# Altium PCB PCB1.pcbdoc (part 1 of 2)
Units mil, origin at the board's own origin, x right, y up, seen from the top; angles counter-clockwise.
Board outline 5175 x 2060 mil, 4 copper layers (Top Layer, Inner1, Inner2, Bottom Layer), stack 62.447 mil thick; 105 components, 59 nets, 317 pads, 174 vias.
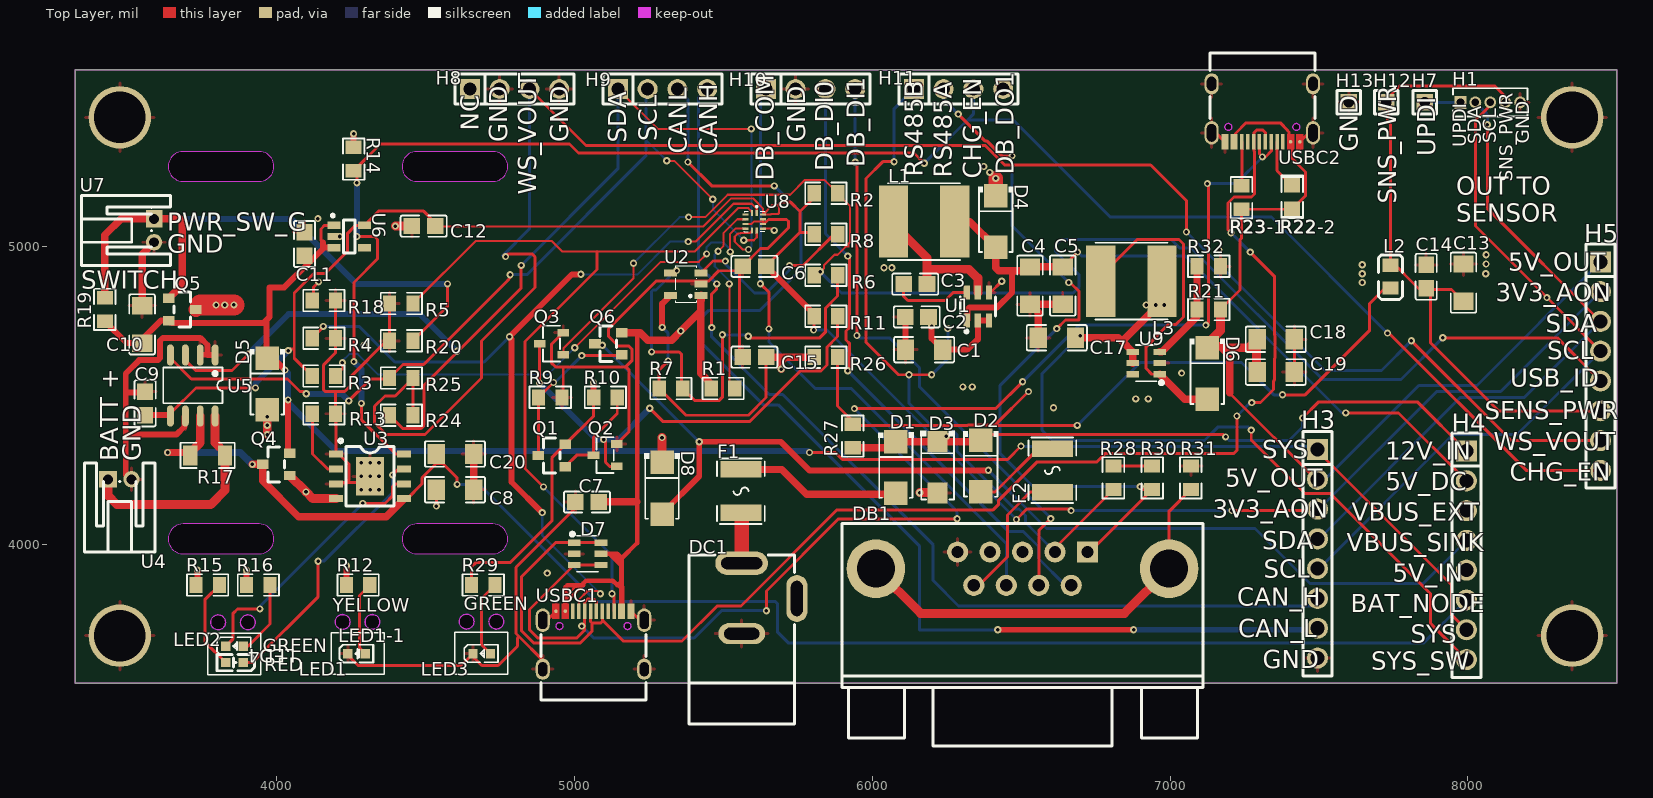
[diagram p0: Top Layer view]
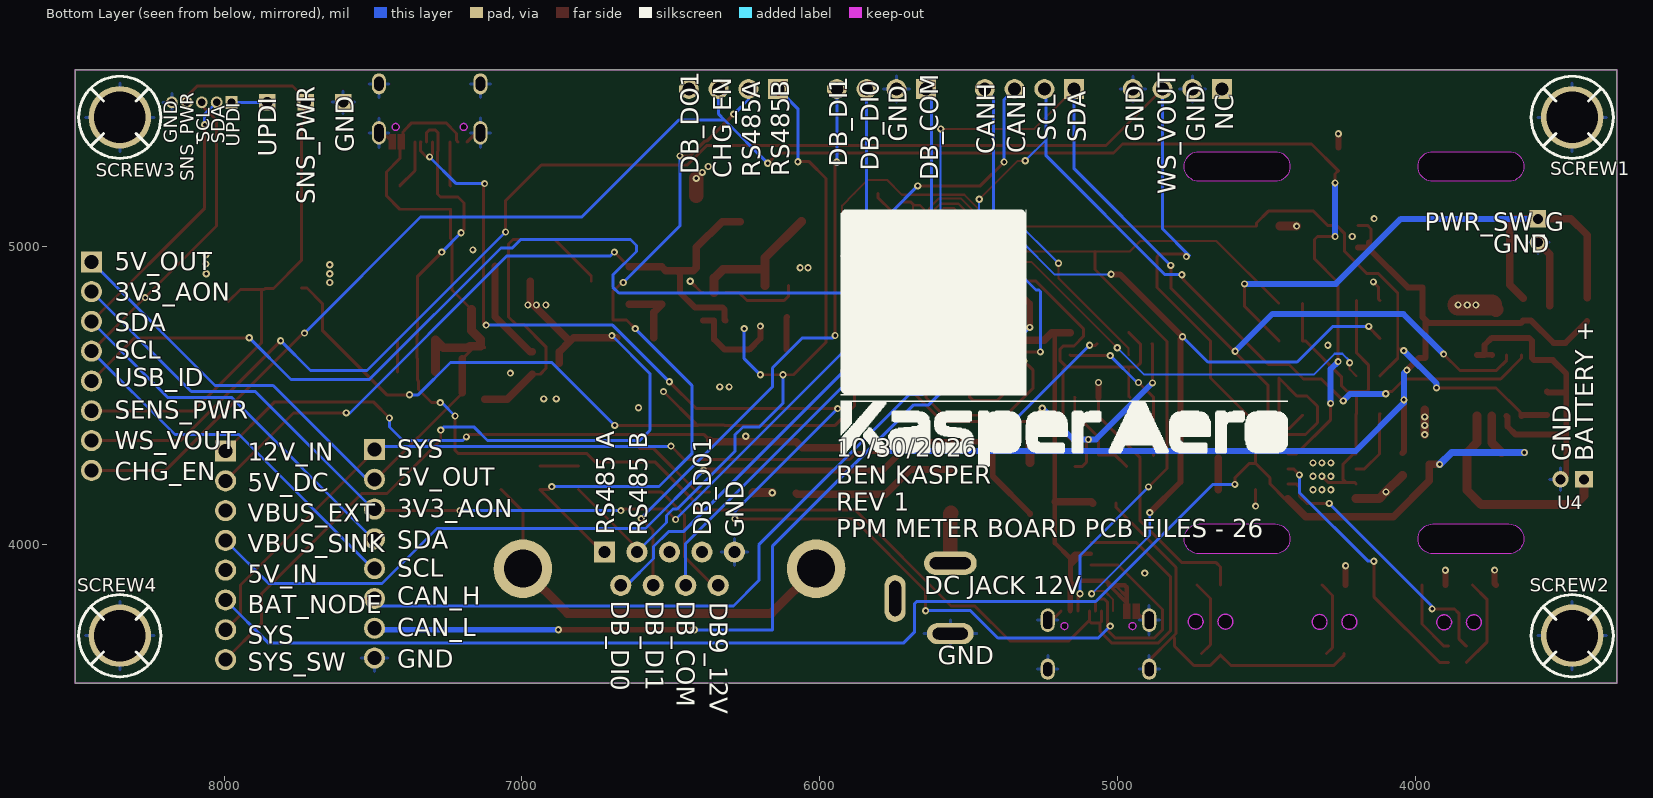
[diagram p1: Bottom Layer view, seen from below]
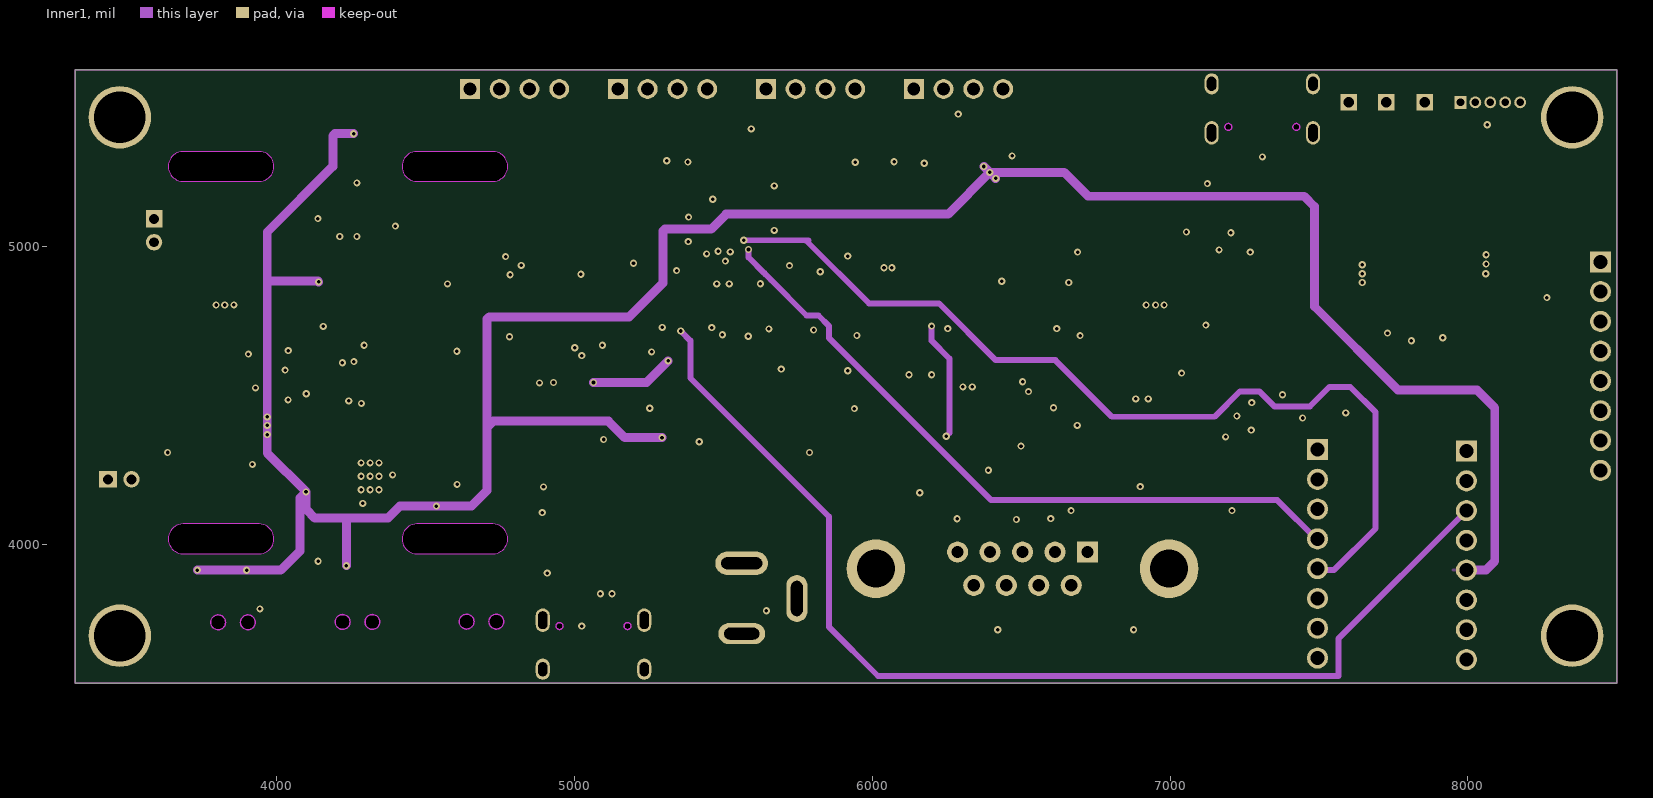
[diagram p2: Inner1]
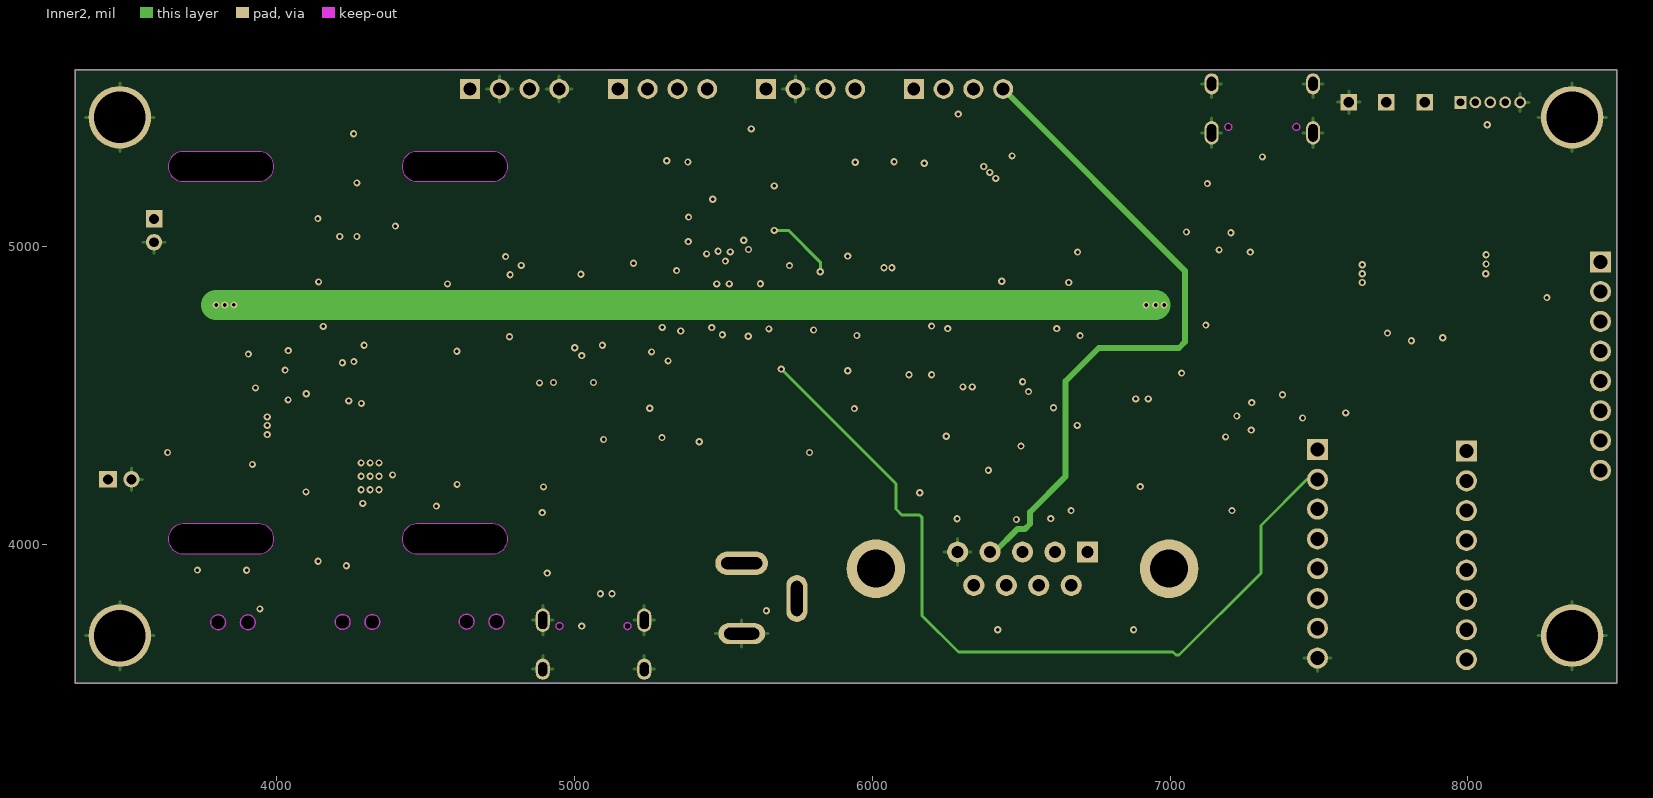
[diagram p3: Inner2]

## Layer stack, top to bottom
Top Layer: signal copper 1.378
Dielectric1: surface 8.283, 7628 RC49% 8.6mil, Dk 0
Inner1: signal copper 0.598
Dielectric2: surface 41.929, 1.1mm H/HOZ Copper, Dk 0
Inner2: signal copper 0.598
Dielectric3: surface 8.283, 7628 RC49% 8.6mil, Dk 0
Bottom Layer: signal copper 1.378

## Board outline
3325,5595 3325,3535 8500,3535 8500,5595
cut-out: 3687.5,5320 ccw(c3687.5,5270) 3637.5,5270 ccw(c3687.5,5270) 3687.5,5220 3942.5,5220 ccw(c3942.5,5270) 3992.5,5270 ccw(c3942.5,5270) 3942.5,5320
cut-out: 4472.5,5320 ccw(c4472.5,5270) 4422.5,5270 ccw(c4472.5,5270) 4472.5,5220 4727.5,5220 ccw(c4727.5,5270) 4777.5,5270 ccw(c4727.5,5270) 4727.5,5320
cut-out: 3687.5,4070 ccw(c3687.5,4020) 3637.5,4020 ccw(c3687.5,4020) 3687.5,3970 3942.5,3970 ccw(c3942.5,4020) 3992.5,4020 ccw(c3942.5,4020) 3942.5,4070
cut-out: 4472.5,4070 ccw(c4472.5,4020) 4422.5,4020 ccw(c4472.5,4020) 4472.5,3970 4727.5,3970 ccw(c4727.5,4020) 4777.5,4020 ccw(c4727.5,4020) 4727.5,4070
cut-out: 3830,3740 cw(c3805,3740) 3780,3740 cw(c3805,3740)
cut-out: 3930,3740 cw(c3905,3740) 3880,3740 cw(c3905,3740)
cut-out: 4248,3741.25 cw(c4223,3741.25) 4198,3741.25 cw(c4223,3741.25)
cut-out: 4348,3741.25 cw(c4323,3741.25) 4298,3741.25 cw(c4323,3741.25)
cut-out: 4664,3742.25 cw(c4639,3742.25) 4614,3742.25 cw(c4639,3742.25)
cut-out: 4764,3742.3 cw(c4739,3742.3) 4714,3742.3 cw(c4739,3742.3)

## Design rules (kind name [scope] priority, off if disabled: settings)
BoardOutlineClearance copperThickness1oz [All] p0: genericclearance=10 ignorepadtopadclearanceinfootprint=FALSE except(0: Arc-SplitContinuation Track-SplitContinuation SMDPad-SplitContinuation THPad-SplitContinuation Via-SplitContinuation Fill-SplitContinuation Poly-SplitContinuation Region-SplitContinuation Text-SplitContinuation)
BoardOutlineClearance copperThickness2oz [All] p0: genericclearance=10 ignorepadtopadclearanceinfootprint=FALSE except(0: Arc-SplitContinuation Track-SplitContinuation SMDPad-SplitContinuation THPad-SplitContinuation Via-SplitContinuation Fill-SplitContinuation Poly-SplitContinuation Region-SplitContinuation Text-SplitContinuation)
BoardOutlineClearance safeClearance1 [All] p0: genericclearance=10 ignorepadtopadclearanceinfootprint=FALSE except(0: Arc-SplitContinuation Track-SplitContinuation SMDPad-SplitContinuation THPad-SplitContinuation Via-SplitContinuation Fill-SplitContinuation Poly-SplitContinuation Region-SplitContinuation Text-SplitContinuation)
BoardOutlineClearance otherClearance [All] p0: genericclearance=10 ignorepadtopadclearanceinfootprint=FALSE except(0: Arc-SplitContinuation Track-SplitContinuation SMDPad-SplitContinuation THPad-SplitContinuation Via-SplitContinuation Fill-SplitContinuation Poly-SplitContinuation Region-SplitContinuation Text-SplitContinuation)
Clearance copperThickness1oz [All] p1: gap=7 ignorepadtopadclearanceinfootprint=FALSE
Clearance copperThickness2oz [All] p1: gap=7 ignorepadtopadclearanceinfootprint=FALSE
Clearance safeClearance1 [All] p1: gap=7 ignorepadtopadclearanceinfootprint=FALSE
Clearance otherClearance [All] p1: gap=7 ignorepadtopadclearanceinfootprint=FALSE
DiffPairsRouting differentialPair [All] p1: maxuncoupledlength=10 minlimit=6 maxlimit=Infinity mostfreqgap=6 toplayer_minwidth=5 toplayer_prefwidth=10 toplayer_maxwidth=100 bottomlayer_minwidth=5 bottomlayer_prefwidth=10 bottomlayer_maxwidth=100 midlayer1_minwidth=5 midlayer1_prefwidth=10 midlayer1_maxwidth=100 midlayer2_minwidth=5 midlayer2_prefwidth=10 midlayer2_maxwidth=100
PasteMaskExpansion pasteMaskExpansion [All] p1: expansion=0
PlaneConnect innerPlane [All] p1: planeconnectstyle=Relief reliefexpansion=20 reliefentries=4 reliefconductorwidth=10 reliefairgap=10
PolygonConnect copperRegion [All] p1: connectstyle=Relief reliefentries=4 reliefconductorwidth=10 polygonreliefangle="90 Angle" airgapwidth=10
RoutingVias viaSize [All] p1: viastyle="Through Hole" holewidth=12.0078 minholewidth=11.811 maxholewidth=248.0314 width=12.0078 minwidth=11.811 maxwidth=248.0314
SolderMaskExpansion solderMaskExpansion [IsVia] p1: useseparateexpansions=TRUE expansion=-1000 expansionbottom=-1000
SolderMaskExpansion solderMaskExpansion [All] p2: useseparateexpansions=TRUE expansion=2 expansionbottom=2
Width copperThickness1oz [All] p1: maxlimit=100 minlimit=5 preferedwidth=10
Width copperThickness2oz [All] p1: maxlimit=100 minlimit=8 preferedwidth=10

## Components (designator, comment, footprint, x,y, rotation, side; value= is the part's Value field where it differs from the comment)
C1 "22uF" C1206 6175,4655 r0 top
C2 "100nF" C0805 6150,4765 r0 top
C3 "100nF" C0805 6145,4875 r180 top
C4 "22uF" C1206 6530,4870 r90 top
C5 "22uF" C1206 6640,4870 r90 top
C6 "100nF" C0805 5605,4935 r0 top
C7 "1uF" C0805 5043.2,4143.7 r180 top
C8 "22uF" C1206 4600,4185 r180 top
C9 "100nF" C0805 3560,4475 r270 top
C10 "22uF" C1206 3550,4740 r270 top
C11 "1uF" C0805 4095,5010 r270 top
C12 "1uF" C0805 4495,5070 r0 top
C13 "22uF" C1206 7985,4880 r90 top
C14 "100nF" C0805 7860,4900 r270 top
C15 "100nF" C0805 5605,4630 r0 top
C17 "22uF" C1206 6620,4695 r180 top
C18 "22uF" C1206 7355,4690 r0 top
C19 "22uF" C1206 7355,4580 r0 top
C20 "22uF" C1206 4600,4305 r180 top
D1 "SS34" SMA_L4.3-W2.6-LS5.2-RD 6080,4260 r270 top
D2 "SS34" SMA_L4.3-W2.6-LS5.2-RD 6365,4264.23 r270 top
D3 "SMAJ18A" SMA_L4.4-W2.6-LS5.0-RD 6220,4260 r270 top
D4 "SS34" SMA_L4.3-W2.6-LS5.2-RD 6415,5085 r270 top
D5 "SS34" SMA_L4.3-W2.6-LS5.2-RD 3970,4540 r270 top
D6 "SS34" SMA_L4.3-W2.6-LS5.2-RD 7125,4575 r270 top
D7 "USBLC6-2SC6" SOT-23-6_L2.9-W1.6-P0.95-LS2.8-BL 5045,3970 r270 top
D8 "SS34" SMA_L4.3-W2.6-LS5.2-RD 5295,4190 r270 top
DB1 "A-DF 09 A/KG-T2S" DB9-TH_DB9F_C9900018961 6505,3920 r0 top
DC1 "PJ-002AH" DC-IN-TH_PJ-002AH 5655,3820 r270 top
F1 "BSMD1812-150-33V" F1812 5560,4180 r90 top
F2 "BSMD1812-150-33V" F1812 6605,4250 r90 top
H1 "GRPB051VWVN-RC" HDR-TH_5P-P1.27-V-M-1 8075,5485 r0 top
H3 "" HDR-TH_8P-P2.54-V-F-1 7495,3970 r270 top
H4 "" HDR-TH_8P-P2.54-V-F-1 7995,3965 r270 top
H5 "" HDR-TH_8P-P2.54-V-F-1 8445,4600 r270 top
H7 "" HDR-TH_1P-V-M_XKB_X4611WV-01I-C28D40 7855,5485.98 r0 top
H8 "" HDR-TH_4P-P2.54-V-M 4800,5530 r0 top
H9 "" HDR-TH_4P-P2.54-V-M 5296.67,5530 r0 top
H10 "" HDR-TH_4P-P2.54-V-M 5793.33,5530 r0 top
H11 "" HDR-TH_4P-P2.54-V-M 6290,5530 r0 top
H12 "" HDR-TH_1P-V-M_XKB_X4611WV-01I-C28D40 7726.37,5485.98 r0 top
H13 "" HDR-TH_1P-V-M_XKB_X4611WV-01I-C28D40 7600,5485.98 r0 top
L1 "6.8uH" IND-SMD_L6.0-W6.0_SMNR6045 6175,5085 r180 top
L2 "BLM21PG221SN1D" L0805 7740,4900 r90 top
L3 "6.8uH" IND-SMD_L6.0-W6.0_SMNR6045 6870,4885 r0 top
LED1 "KT-0603Y" LED0603-R-RD 4270,3635 r0 top
LED1-1 "NCD0603Y2" LED0603-RD 4270,3635 r0 top
LED2 "KT-0603G" LED0603-RD 3860,3660 r0 top
LED3 "KT-0603G" LED0603-RD 4690,3635 r0 top
LED4 "KT-0603R" LED-SMD_L1.6-W0.8-R-RD 3860,3605 r180 top
Q1 "AO3401A" SOT-23_L2.9-W1.3-P1.90-LS2.4-BR 4925,4300 r0 top
Q2 "2N7002" SOT-23-3_L2.9-W1.3-P1.90-LS2.4-BR 5104.1,4300.97 r0 top
Q3 "2N7002" SOT-23-3_L2.9-W1.3-P1.90-LS2.4-BR 4924.1,4675 r0 top
Q4 "AO3401A" SOT-23_L2.9-W1.3-P1.90-LS2.4-BR 4000,4270 r0 top
Q5 "AO3401A" SOT-23_L2.9-W1.3-P1.90-LS2.4-BR 3685,4790 r180 top
Q6 "AO3401A" SOT-23_L2.9-W1.3-P1.90-LS2.4-BR 5115,4675 r0 top
R1 "910kΩ" R0805 5500,4525 r0 top
R2 "100kΩ" R0805 5845,5180 r0 top
R3 "100kΩ" R0805 4160,4566.67 r0 top
R4 "5.1kΩ" R0805 4160,4693.33 r0 top
R5 "5.1kΩ" R0805 4420,4810 r180 top
R6 "0Ω" R0805 5845,4905 r0 top
R7 "100kΩ" R0805 5325,4525 r0 top
R8 "10kΩ" R0805 5845,5042.5 r0 top
R9 "100kΩ" R0805 4920,4495 r0 top
R10 "100kΩ" R0805 5105,4495 r0 top
R11 "100kΩ" R0805 5845,4767.5 r0 top
R12 "1kΩ" R0805 4275,3865 r0 top
R13 "2kΩ" R0805 4160,4440 r0 top
R14 "10kΩ" R0805 4260,5295 r270 top
R15 "1kΩ" R0805 3770,3865 r0 top
R16 "1kΩ" R0805 3940,3865 r0 top
R17 "50mΩ" R1206 3770,4300 r180 top
R18 "100kΩ" R0805 4160,4820 r180 top
R19 "1kΩ" R0805 3425,4790 r90 top
R20 "0Ω" R0805 4420,4685 r180 top
R21 "75kΩ" R0805 7130,4790 r180 top
R22 "56kΩ" R0805 7410,5165.78 r90 top
R22-2 "10kΩ" R0805 7410,5170 r90 top
R23 "56kΩ" R0805 7240,5165.78 r90 top
R23-1 "10kΩ" R0805 7240,5165 r90 top
R24 "10kΩ" R0805 4420,4435 r0 top
R25 "10kΩ" R0805 4420,4560 r0 top
R26 "0Ω" R0805 5845,4630 r0 top
R27 "0Ω" R0805 5935,4365 r90 top
R28 "0Ω" R0805 6810,4225 r270 top
R29 "1kΩ" R0805 4695,3865 r0 top
R30 "120Ω" R0805 6940,4225 r90 top
R31 "0Ω" R0805 7070,4225 r90 top
R32 "10kΩ" R0805 7130,4935 r0 top
SCREW1 "" Screw-Hole-M4 3475,5434.98 r180 bottom
SCREW2 "" Screw-Hole-M4 3475,3695 r180 bottom
SCREW3 "" Screw-Hole-M4 8350,5435 r180 bottom
SCREW4 "" Screw-Hole-M4 8350,3695 r180 bottom
U1 "AP63205WU-7" TSOT-23-6_L2.9-W1.6-P0.95-LS2.8-BL 6355,4800 r0 top
U2 "TPS2041BDBVR" SOT-23-5_L3.0-W1.7-P0.95-LS2.8-BR 5375,4875 r0 top
U3 "TP4056-42-ESOP8" ESOP-8_L4.9-W3.9-P1.27-LS6.0-BL-EP 4315,4230 r270 top
U4 "S2B-PH-K-S(LF)(SN)" CONN-TH_S2B-PH-K-S-LF-SN 3475,4220 r180 top
U5 "INA219AIDR" SOIC-8_L4.9-W3.9-P1.27-LS6.0-BL 3720,4535 r180 top
U6 "AP2112K-3.3TRG1" SOT-25-5_L2.9-W1.6-P0.95-LS2.8-BL 4245,5035 r270 top
U7 "S2B-PH-K-S(LF)(SN)" CONN-TH_S2B-PH-K-S-LF-SN 3590,5055 r90 top
U8 "TUSB320IRWBR" X2QFN-12_L1.6-W1.6-P0.40-TL 5605,5085 r270 top
U9 "MT3608" SOT-23-6_L2.9-W1.6-P0.95-LS2.8-BL 6920,4610 r90 top
USBC1 "TYPE-C-31-M-12" USB-C_SMD-TYPE-C-31-M-12_1 5065,3680 r0 top
USBC2 "TYPE-C-31-M-12" USB-C_SMD-TYPE-C-31-M-12_1 7310,5450 r180 top

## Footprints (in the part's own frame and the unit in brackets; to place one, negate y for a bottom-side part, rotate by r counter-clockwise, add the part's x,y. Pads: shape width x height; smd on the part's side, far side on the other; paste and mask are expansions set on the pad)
C0805 [mm]
  rect 1.41x1.35 smd paste-100 mask+0.051: 1(-1,0) 2(1,0)
  silkscreen extent -1.96,-0.9 1.96,0.9
C1206 [mm]
  rect 1.485x1.728 smd paste-100 mask+0.051: 1(-1.593,0) 2(1.593,0)
  silkscreen extent -2.56,-1.09 2.56,1.09
CONN-TH_S2B-PH-K-S-LF-SN [mm]
  rect 1.5x1.4 hole 0.85: 1(1,0)
  round 1.4 hole 0.85: 2(-1,0)
  silkscreen extent -3,-1.4 3,6.2
DB9-TH_DB9F_C9900018961 [mm]
  rect 1.8x1.8 hole 1.05 paste+0 mask+0.05: 1(5.54,1.42)
  round 1.8 hole 1.05 paste+0 mask+0.05: 2(2.77,1.42) 3(0,1.42) 4(-2.77,1.42) 5(-5.54,1.42) 6(4.155,-1.42) 7(1.385,-1.42) 8(-1.385,-1.42) 9(-4.155,-1.42)
  round 5 hole 3.25 paste+0 mask+0.05: 10(-12.5,0) 11(12.5,0)
  silkscreen extent -15.4,-15.13 15.4,3.87
DC-IN-TH_PJ-002AH [mm]
  oval 2x4.5 hole 1 slot 3.5 at 90 deg copper offset 0.001,0: 1(-3.001,-2.35)
  oval 1.8x4 hole 1 slot 3 at 90 deg copper offset 0,0: 2(3,-2.35)
  oval 4x1.8 hole 1 slot 3 at 0 deg copper offset 0,0.001: 3(0,2.349)
  silkscreen extent -3.7,-6.85 10.7,2.15
ESOP-8_L4.9-W3.9-P1.27-LS6.0-BL-EP [mm]
  rect 0.6x1.2 smd: 1(-1.905,-2.908) 2(-0.635,-2.908) 3(0.635,-2.908) 4(1.905,-2.908) 5(1.905,2.908) 6(0.635,2.908) 7(-0.635,2.908) 8(-1.905,2.908)
  rect 3.3x2.4 smd: 9(0,0)
  silkscreen extent -3.2,-2.67 2.55,2.05
F1812 [mil]
  rect 55.38x137.76 smd paste-3937.01 mask+2: 1(-72.97,0) 2(72.97,0)
  silkscreen extent -110,-80 110,80
HDR-TH_1P-V-M_XKB_X4611WV-01I-C28D40 [mm]
  rect 1.4x1.4 hole 0.9: 1(0,0)
  silkscreen extent -1,-1 1,1
HDR-TH_4P-P2.54-V-M [mm]
  rect 1.7x1.7 hole 1.1: 1(-3.81,0)
  round 1.7 hole 1.1: 2(-1.27,0) 3(1.27,0) 4(3.81,0)
  silkscreen extent -5.08,-1.27 5.08,1.27
HDR-TH_5P-P1.27-V-M-1 [mm]
  rect 1x1.1 hole 0.65: 1(-2.54,0)
  round 1 hole 0.65: 2(-1.27,0) 3(0,0) 4(1.27,0) 5(2.54,0)
  silkscreen extent -3.17,-1.2 3.17,1.2
HDR-TH_8P-P2.54-V-F-1 [mm]
  rect 1.8x1.8 hole 1.2: 1(-8.89,0)
  round 1.8 hole 1.2: 2(-6.35,0) 3(-3.81,0) 4(-1.27,0) 5(1.27,0) 6(3.81,0) 7(6.35,0) 8(8.89,0)
  silkscreen extent -10.41,-1.25 10.41,1.25
IND-SMD_L6.0-W6.0_SMNR6045 [mm]
  rect 2.474x6.12 smd: 1(2.603,0) 2(-2.603,0)
  silkscreen extent -3.08,-3.28 3.08,3.28
L0805 [mil]
  rect 44.59x54.21 smd paste-3937.01 mask+2: 1(-38.04,0) 2(38.04,0)
  silkscreen extent -77,-40 73,40
LED0603-R-RD [mm]
  rect 0.8x0.8 smd: 1(0.751,0) 2(-0.751,0)
  silkscreen extent -1.44,-0.75 1.44,0.75
LED0603-RD [mm]
  rect 0.8x0.8 smd: 1(-0.749,0) 2(0.749,0)
  silkscreen extent -1.49,-0.75 1.39,0.76
LED-SMD_L1.6-W0.8-R-RD [mm]
  rect 0.8x0.8 smd: 1(0.75,0) 2(-0.75,0)
  silkscreen extent -1.7,-0.7 1.47,0.7
R0805 [mm]
  rect 1.133x1.377 smd paste-100 mask+0.051: 1(-1,0) 2(1,0)
  silkscreen extent -1.76,-0.92 1.76,0.92
R1206 [mil]
  rect 47.54x66.97 smd paste-3937.01 mask+2: 1(-58.22,0) 2(58.22,0)
  silkscreen extent -91,-42 91,42
Screw-Hole-M4 [mil]
  round 210 hole 173.2: 1(0,0)
  silkscreen extent -138,-138 138,138
SMA_L4.3-W2.6-LS5.2-RD [mm]
  rect 2x2 smd: 1(-2.2,0) 2(2.2,0)
  silkscreen extent -2.98,-1.5 2.6,1.5
SMA_L4.4-W2.6-LS5.0-RD [mm]
  rect 1.8x1.7 smd paste+0 mask+0.051: 1(-2.192,0) 2(2.192,0)
  silkscreen extent -3.11,-1.48 2.73,1.48
SOIC-8_L4.9-W3.9-P1.27-LS6.0-BL [mm]
  oval 0.588x1.8 smd paste+0 mask+0.051: 1(-1.905,-2.6) 2(-0.635,-2.6) 3(0.635,-2.6) 4(1.905,-2.6) 5(1.905,2.6) 6(0.635,2.6) 7(-0.635,2.6) 8(-1.905,2.6)
  silkscreen extent -2.53,-1.52 2.53,1.52
SOT-23-3_L2.9-W1.3-P1.90-LS2.4-BR [mm]
  rect 1x0.65 smd: 1(1,-0.95) 2(1,0.95) 3(-1,0)
  silkscreen extent -0.73,-1.53 0.73,1.53
SOT-23-5_L3.0-W1.7-P0.95-LS2.8-BR [mm]
  rect 1.1x0.6 smd: 1(1.3,-0.95) 2(1.3,0) 3(1.3,0.95) 4(-1.3,0.95) 5(-1.3,-0.95)
  silkscreen extent -0.9,-1.55 0.9,1.55
SOT-23-6_L2.9-W1.6-P0.95-LS2.8-BL [mil]
  rect 20.95x42.2 smd: 1(-37.4,-45.24) 2(0,-45.24) 3(37.4,-45.24) 4(37.4,45.24) 5(0,45.24) 6(-37.4,45.24)
  silkscreen extent -72,-57 61,35
SOT-23_L2.9-W1.3-P1.90-LS2.4-BR [mm]
  rect 1x0.8 smd: 1(1.15,-0.95) 2(1.15,0.95) 3(-1.15,0)
  silkscreen extent -0.7,-1.5 0.7,1.5
SOT-25-5_L2.9-W1.6-P0.95-LS2.8-BL [mil]
  rect 24.5x43.5 smd: 1(-37.39,-51.18) 2(-0.02,-51.18) 3(37.39,-51.18) 4(37.39,51.18) 5(-37.39,51.18)
  silkscreen extent -75,-60 56,20
TSOT-23-6_L2.9-W1.6-P0.95-LS2.8-BL [mm]
  rect 0.55x1.2 smd: 1(-0.95,-1.2) 2(0,-1.2) 3(0.95,-1.2) 4(0.95,1.2) 5(0,1.2) 6(-0.95,1.2)
  silkscreen extent -1.5,-2.25 1.5,0.8
USB-C_SMD-TYPE-C-31-M-12_1 [mm]
  oval 1.2x2 hole 0.8 slot 1.5 at 90 deg paste+0 mask+0.051: 1(4.325,1.706) 4(-4.325,1.706)
  oval 1.2x1.8 hole 0.8 slot 1.2 at 90 deg copper offset 0,0 paste+0 mask+0.051: 2(4.325,-2.474) 3(-4.325,-2.474)
  round 0.3 smd: A1B12(-3.2,2.474) A4B9(-2.4,2.474)
  rect 0.3x1.3 smd paste-100 mask+0.051: A5(-1.25,2.474) A6(-0.25,2.474) A7(0.25,2.474) A8(1.25,2.474) B5(1.75,2.474) B6(0.75,2.474) B7(-0.75,2.474) B8(-1.75,2.474)
  rect 0.6x1.3 smd paste-100 mask+0.051: B1A12(3.2,2.474) B4A9(2.4,2.474)
  Top Layer region: -2.9,1.824 -2.9,3.124 -3.2,3.124 -3.2,3.124 -3.5,3.124 -3.5,1.824 -3.2,1.824 -3.2,1.824
  Top Layer region: -2.1,1.824 -2.1,3.124 -2.4,3.124 -2.4,3.124 -2.7,3.124 -2.7,1.824 -2.4,1.824 -2.4,1.824
  Board Outline Layer circle w0.003: c-2.9,1.206 r0.3
  Board Outline Layer circle w0.003: c2.9,1.206 r0.3
  Board Outline Layer region: -2.6,1.206 -2.63,1.075 -2.713,0.971 -2.833,0.913 -2.967,0.913 -3.087,0.971 -3.17,1.075 -3.2,1.206 -3.2,1.206 -3.17,1.336 -3.087,1.44 -2.967,1.498 -2.833,1.498 -2.713,1.44 -2.63,1.336 -2.6,1.206
  Board Outline Layer region: -2.6,1.206 -2.609,1.134 -2.634,1.066 -2.675,1.007 -2.729,0.959 -2.794,0.925 -2.864,0.908 -2.936,0.908 -3.006,0.925 -3.07,0.959 -3.124,1.007 -3.166,1.066 -3.191,1.134 -3.2,1.206 -3.191,1.277 -3.166,1.345 -3.124,1.405 -3.07,1.453 -3.006,1.486 -2.936,1.503 -2.864,1.503 -2.794,1.486 -2.729,1.453 -2.675,1.405 -2.634,1.345 -2.609,1.277
  Board Outline Layer region: 3.2,1.206 3.17,1.075 3.087,0.971 2.967,0.913 2.833,0.913 2.713,0.971 2.63,1.075 2.6,1.206 2.6,1.206 2.63,1.336 2.713,1.44 2.833,1.498 2.967,1.498 3.087,1.44 3.17,1.336 3.2,1.206
  Board Outline Layer region: 3.2,1.206 3.191,1.134 3.166,1.066 3.124,1.007 3.07,0.959 3.006,0.925 2.936,0.908 2.864,0.908 2.794,0.925 2.729,0.959 2.675,1.007 2.634,1.066 2.609,1.134 2.6,1.206 2.609,1.277 2.634,1.345 2.675,1.405 2.729,1.453 2.794,1.486 2.864,1.503 2.936,1.503 3.006,1.486 3.07,1.453 3.124,1.405 3.166,1.345 3.191,1.277
  Multi-Layer board cut-out: -2.6,1.206 -2.63,1.075 -2.713,0.971 -2.833,0.913 -2.967,0.913 -3.087,0.971 -3.17,1.075 -3.2,1.206 -3.2,1.206 -3.17,1.336 -3.087,1.44 -2.967,1.498 -2.833,1.498 -2.713,1.44 -2.63,1.336 -2.6,1.206
  Multi-Layer board cut-out: 3.2,1.206 3.17,1.075 3.087,0.971 2.967,0.913 2.833,0.913 2.713,0.971 2.63,1.075 2.6,1.206 2.6,1.206 2.63,1.336 2.713,1.44 2.833,1.498 2.967,1.498 3.087,1.44 3.17,1.336 3.2,1.206
  silkscreen extent -4.47,-5.09 4.47,0.49
X2QFN-12_L1.6-W1.6-P0.40-TL [mm]
  rect 0.505x0.2 smd: 1(-0.75,0.2) 2(-0.75,-0.2) 7(0.75,-0.2) 8(0.75,0.2)
  rect 0.2x0.505 smd: 3(-0.6,-0.75) 4(-0.2,-0.75) 5(0.2,-0.75) 6(0.6,-0.75) 9(0.6,0.75) 10(0.2,0.75) 11(-0.2,0.75) 12(-0.6,0.75)
  silkscreen extent -1.35,-0.87 0.86,0.87

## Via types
v1: diameter 24.02, hole 12, Top Layer to Bottom Layer, 174 vias

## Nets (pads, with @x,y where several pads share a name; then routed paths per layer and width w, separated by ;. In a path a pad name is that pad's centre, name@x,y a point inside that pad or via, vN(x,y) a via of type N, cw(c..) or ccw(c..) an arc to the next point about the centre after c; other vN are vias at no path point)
3V3_AON: C6.2 C9.2 C12.2 H3.3 H5.2 R2.1 R3.1 R8.1 R11.1 U5.5 U6.5 U8.12 | length 6842.2
  Top Layer w7.09: C12.2@4534.37,5070 4535.75,5068.62 5433.62,5068.62 5527.91,5162.91 5600.24,5162.91 5634.53,5128.62 U8.12@5634.53,5108.62 ; 5687.73,5113.88 5684.49,5110.64 5661.92,5110.64 5659.9,5108.62 U8.12@5634.53,5108.62 ; 5688.09,5114.24 5688.09,5136.28 5684.37,5140 5664.37,5140 U8.12@5634.53,5108.62
  Top Layer w10: U5.5@3645,4432.63 3650.63,4438.27 3650.63,4446.84 3730.63,4526.84 v1(3930.63,4526.84) ; v1(4040.63,4651.84) 4045.63,4656.84 4060.63,4656.84 ; R3.1@4120.63,4566.67 4060.63,4626.67 4060.63,4656.84 ; C12.2@4534.37,5070 4534.37,5080.63 4495,5120 4343.79,5120 U6.5@4296.18,5072.39 4266.18,5072.39 4240,5046.21 4240,4986.21 4163.79,4910 4125,4910 4060.63,4845.63 4060.63,4656.84 ; C6.2@5644.37,4935 5758.51,5049.14 ; 5684.37,5140 5694.37,5150 5727.02,5150 5758.51,5118.51 ; v1(5803.68,4721.01) 5805.63,4722.95 R11.1@5805.63,4767.5 ; R8.1@5805.63,5042.5 5798.99,5049.14 5758.51,5049.14 ; R2.1@5805.63,5180 5805.63,5165.63 5758.51,5118.51 ; v1(6484.44,4084.99) 6519.46,4120 6663.13,4120 v1(6668.13,4115) ; v1(7208.13,4115) H3.3@7495,4115 ; 5758.51,5049.14 5758.51,5118.51
  Top Layer w20: C9.2@3560,4435.63 3642.01,4435.63 U5.5@3645,4432.63 ; C6.2@5644.37,4935 5805.63,4773.74 R11.1@5805.63,4767.5
  Bottom Layer w10: v1(5803.68,4721.01) 5848.42,4721.01 v1(6484.44,4084.99) ; v1(6668.13,4115) v1(7208.13,4115) ; H3.3@7495,4115 7895,4515 8110,4515 H5.2@8445,4850
  Bottom Layer w20: v1(3930.63,4526.84) 3930.63,4541.84 v1(4040.63,4651.84)
5V_DC: C4.2 C5.2 D4.2 H4.2 L1.2 U1.1 | length 2468.8
  Top Layer w10: C5.2@6640,4932.7 v1(6690,4982.7) ; v1(7590,4442.7) 7767.29,4442.7 H4.2@7995,4215
  Top Layer w20: U1.1@6317.6,4752.76 6320,4755.16 6320,4790 6327.07,4797.07 6420,4797.07 6470,4847.07 6470,4909.53 6480.47,4920
  Top Layer w25: L1.2@6267.48,5085 6328.39,5085 D4.2@6415,4998.39 6415,4930 ; 6415,4929.53 6424.53,4920 6480.47,4920 6517.3,4920 C4.2@6530,4932.7 C5.2@6640,4932.7
  Bottom Layer w10: v1(6690,4982.7) 6702.7,4970 7050,4970 7577.3,4442.7 v1(7590,4442.7)
5V_IN: C8.2 D4.1 D5.2 D8.1 H4.5 Q4.1 R12.1 R14.1 R15.1 R16.1 R18.2 U3.4 | length 9878.7
  Top Layer w10: R18.2@4120.63,4820 4125,4824.37 4125,4865 v1(4142.5,4882.5) ; C8.2@4537.3,4185 4537.66,4184.64 v1(4537.66,4130)
  Top Layer w20: R15.1@3730.63,3865 3735.63,3870 v1(3735.63,3915.04) ; R16.1@3900.63,3865 v1(3900.63,3915) ; R12.1@4235.63,3865 v1(4235.63,3930) ; R14.1@4260,5334.37 v1(4260,5380)
  Top Layer w30: v1(3970,4370) v1(3970,4400.76) v1(3970,4429.31) D5.2@3970,4453.39 ; Q4.1@4045.28,4232.6 v1(4100.14,4177.74) 4122.88,4155 U3.4@4200.5,4155 ; D8.1@5295,4276.61 v1(5295,4360)
  Top Layer w50: D4.1@6415,5171.61 v1(6415,5230)
  Inner1 w30: v1@3735.67,3915 v1(3900.63,3915) 4015,3915 4080,3980 4080,4157.6 v1(4100.14,4177.74) ; v1(4142.5,4882.5) 4139.84,4885.16 3970,4885.16 ; v1(4235.63,3930) 4235.63,4085.99 4239.64,4090 ; v1(4260,5380) 4197.07,5380 4190,5372.93 4190,5270 3970,5050 3970,4885.16 ; v1(5295,4360) 5170,4360 5115,4415 4729,4415 4707.93,4393.93 ; v1(6375,5270) v1(6395,5250) ; v1(6415,5230) v1(6395,5250) ; H4.5@7995,3915 8060,3915 8090,3945 8090,4460 8030,4520 7765,4520 7485,4800 7485,5135 7450,5170 6725,5170 6645,5250 v1(6395,5250) ; 3970,4885.16 v1(3970,4429.31) v1(3970,4400.76) v1(3970,4370) 3970,4307.88 v1(4100.14,4177.74) ; v1(4100.14,4177.74) 4100.14,4119.86 4130,4090 4239.64,4090 ; 4239.64,4090 4375,4090 4415,4130 v1(4537.66,4130) 4655,4130 4707.93,4182.93 4707.93,4393.93 ; 4707.93,4393.93 4707.93,4757.93 4715,4765 5185,4765 5297.93,4877.93 5297.93,5052.93 5305,5060 5460,5060 5510,5110 6255,5110 v1(6395,5250)
5V_OUT: C15.2 C18.1 C19.1 D6.1 H3.2 H5.1 Q1.2 R7.1 R10.1 R21.1 R22-2.1 R22.1 R23-1.1 R23.1 R26.1 R29.1 U2.5 USBC2.A4B9 USBC2.B4A9 | length 8491.7
  Top Layer w10: R29.1@4655.63,3865 4655.63,3925.63 4670,3940 4785,3940 4925,4080 4925,4292.12 Q1.2@4970.27,4337.4 5065.63,4432.76 R10.1@5065.63,4495 ; v1(5315.63,4617.48) 5285.63,4587.48 R7.1@5285.63,4525 5375.63,4435 5585,4435 5644.37,4494.37 C15.2@5644.37,4630 ; R21.1@7169.37,4790 7235,4855.63 7235,5023.82 7240,5028.82 R23.1@7240,5126.41 R22.1@7410,5126.41 7455,5171.41 7455,5251.41 7410,5296.41 7410,5346.41 ; 7200,4510 H3.2@7495,4215 ; 7200,4625 D6.1@7163.39,4661.61 ; USBC2.B4A9@7215.51,5352.59 7220,5357.09 7220,5381 7255.41,5416.41 7370,5416.41 7394.56,5391.85 7394.56,5390.27 7399,5385.83 7399,5357.41 7410,5346.41 ; C19.1@7290.58,4581.72 C19.1@7292.3,4580 ; USBC2.A4B9@7404.49,5352.6 7410,5347.09 7410,5346.41 ; D6.1@7163.39,4661.61 D6.1@7125,4661.61 D6.1@7163.39,4661.61
  Top Layer w20: v1(5065,4545) 5065,4495.63 R10.1@5065.63,4495 ; v1(5295.63,4730) 5295.63,4809.41 U2.5@5323.81,4837.6
  Top Layer w25: C15.2@5644.37,4630 5709.2,4630 ; v1(5695,4590) 5695,4615.8 5709.2,4630 ; R26.1@5805.63,4630 5709.2,4630 ; 7200,4510 7200,4625
  Top Layer w30: R21.1@7169.37,4790 7169.37,4719.37 7140,4690 7140,4666.61 7175,4666.61 7180,4661.61 7263.91,4661.61 7290.58,4688.28 C19.1@7290.58,4581.72
  Inner1 w30: v1(5065,4545) 5243.15,4545 v1(5315.63,4617.48)
  Inner2 w10: v1(5695,4590) 6080,4205 6080,4120 6100,4100 6160,4100 6167.07,4092.93 6167.07,3762.93 6290,3640 7010,3640 7020,3630 7030,3630 7305,3905 7305,4065 7460,4220 H3.2@7495,4220
  Bottom Layer w10: v1(5295.63,4730) 5315.63,4710 v1(5315.63,4617.48) ; H3.2@7495,4215 7515,4215 7835,4535 8030,4535 H5.1@8445,4950
12V_IN: C1.2 C2.2 D1.1 D2.1 D3.1 H4.1 R27.1 U1.2 U1.3 | length 2952.4
  Top Layer w10: D2.1@6370,4350.84 6390,4370.84 7178.25,4370.84 v1(7186.59,4362.49) ; v1(7445,4425.84) 7499.16,4480 7830,4480 H4.1@7995,4315
  Top Layer w20: v1(6200,4733.99) 6200,4692.7 C1.2@6237.7,4655 6320,4655 6355,4690 U1.2@6355,4752.76 U1.3@6392.4,4752.76
  Top Layer w25: R27.1@5935,4325.63 6059.02,4325.63 D1.1@6080,4346.61 6080.29,4346.32 D3.1@6220,4346.32 6365.48,4346.32 D2.1@6370,4350.84
  Inner1 w20: v1(6200,4733.99) 6200,4685 6260,4625 6260,4375.31 v1(6249.08,4364.39)
  Bottom Layer w10: v1(7186.59,4362.49) 7198.47,4350.61 7399.78,4350.61 7445,4395.84 v1(7445,4425.84)
$1N323: C3.2 U1.6 | length 264.8
  Top Layer w10: C3.2@6105.63,4870 6105.63,4834.37 6120,4820 6245,4820 6272.24,4847.24 U1.6@6317.6,4847.24
BAT_NODE: C20.2 H4.6 Q4.3 R17.2 U3.5 U5.7 | length 5188.8
  Top Layer w10: U3.5@4429.5,4155 4439.5,4155 4489.5,4205 4489.5,4225 C20.2@4537.3,4272.8 ; C20.2@4537.3,4305 C20.2@4537.3,4272.8 ; v1(4607.3,4202.8) 4607.3,4224.68 4559.18,4272.8 C20.2@4537.3,4272.8
  Top Layer w25: v1(3635.65,4310) R17.2@3711.78,4310 ; v1(3920,4270) Q4.3@3954.72,4270 3954.72,4215.27 4075,4095 4369.5,4095 U3.5@4429.5,4155
  Top Layer w30: R17.2@3711.78,4310 3745,4343.22 U5.7@3745,4432.63
  Bottom Layer w10: v1(4607.3,4202.8) 4681.7,4202.8 5074.5,3810 5675,3810 5682.07,3802.93 5682.07,3707.93 5720,3670 7850,3670 H4.6@7995,3815
  Bottom Layer w25: v1(3635.65,4310) 3880,4310 v1(3920,4270)
BATT_P: R17.1 U4.1 U5.8 | length 743.2
  Top Layer w30: U4.1@3435.63,4220 3435.63,4165 3465.63,4135 3780,4135 3828.22,4183.22 3828.22,4310 3795,4343.22 U5.8@3795,4432.63
BOOST_FB: R21.2 R32.1 U9.3 | length 343.7
  Top Layer w25: U9.3@6965.24,4647.4 6972.4,4647.4 7090.63,4765.63 R21.2@7090.63,4790 R32.1@7090.63,4935
BOOST_SW: D6.2 L3.2 U9.1 | length 1084.4
  Top Layer w10: L3.2@6767.52,4885 6767.52,4902.52 6890,5025 7030,5025 7045,5010 7045,4765 7020,4740 6995,4740 6920,4665 6920,4591.74 6939.14,4572.6 U9.1@6965.24,4572.6
  Top Layer w25: U9.1@6965.24,4572.6 7049.45,4488.39 D6.2@7125,4488.39
BUCK_SW: C3.1 L1.1 U1.5 | length 498.7
  Top Layer w30: L1.1@6062.52,5085 6184.37,4963.15 6184.37,4930.79 ; C3.1@6184.37,4870 6184.37,4930.79 ; U1.5@6355,4847.24 6355,4895 6325,4925 6190.16,4925 6184.37,4930.79
CANH: H3.6 H9.4 | length 3362.7
  Top Layer w10: v1(5461.67,4728.99) 5461.67,4841.67 5478.44,4858.44 v1(5478.44,4876.01)
  Bottom Layer w10: H9.4@5446.67,5530 5416.67,5500 5416.67,4937.78 v1(5478.44,4876.01) ; v1(5461.67,4728.99) 5461.67,4698.33 5655,4505 5700,4505 6205,4000 6205,3880 6290,3795 7475,3795 H3.6@7495,3815
CANL: H3.7 H9.3 | length 4022.8
  Top Layer w10: v1(5381.67,5285) 5461.67,5205 v1(5671.67,5205)
  Top Layer w20: v1(6421.67,3715) v1(6878,3715)
  Bottom Layer w10: H9.3@5346.67,5530 5381.67,5495 v1(5381.67,5285) ; v1(5671.67,5205) 5761.67,5115 5761.67,4925 5623.74,4787.07 5452.07,4787.07 5420,4755 5420,4685 5635,4470 5685,4470 6160,3995 6160,3715 v1(6421.67,3715)
  Bottom Layer w20: v1(6878,3715) H3.7@7495,3715
CC1: R4.1 U8.1 USBC1.A5 | length 2915.9
  Top Layer w7.09: USBC1.A5@5015.79,3777.41 5015.79,3815.79 5045,3845 5079.15,3845 v1(5088.14,3836.01) ; v1(5382.87,5018.02) 5408.02,5018.02 5535,5145 5595.89,5145 5612.87,5128.02 U8.1@5612.87,5114.53
  Top Layer w10: R4.1@4120.63,4693.33 4158.19,4730.89 v1(4158.19,4733.33)
  Top Layer w20: v1(4892.87,4108.02) 4790,4210.89 4790,4691.52 v1(4783.19,4698.33) 4992.87,4908.02 v1(5022.87,4908.02)
  Bottom Layer w7.09: v1(4892.87,4108.02) 4892.87,4031.28 v1(5088.14,3836.01) ; v1(5022.87,4908.02) 5213.02,4908.02 5323.02,5018.02 v1(5382.87,5018.02)
  Bottom Layer w10: v1(4158.19,4733.33) 4278.19,4733.33 4398.19,4613.33 4698.19,4613.33 v1(4783.19,4698.33)
CC2: R5.1 U8.2 USBC1.B5 | length 2739.3
  Top Layer w7.09: R5.1@4459.37,4810 4669.37,5020 4925,5020 4960.47,4984.53 5077.13,4984.53 5404.53,4984.53 5550,5130 5585,5130 5595.96,5119.04 5595.96,5115.71 U8.2@5597.13,5114.53
  Top Layer w10: v1(4897.13,4194.53) 4835,4256.66 4835,4682.4 5077.13,4924.53 5077.13,4984.53 ; v1(5127.13,3836.01) 5133.9,3829.24 USBC1.B5@5133.9,3777.41
  Bottom Layer w10: v1(4897.13,4194.53) 5127.13,3964.53 v1(5127.13,3836.01)
CHG_EN: H5.8 H11.3 R14.2 U3.8 | length 6046.7
  Top Layer w10: v1(4260.88,4615) 4260.88,4880.88 4340,4960 4340,5025 4330,5035 v1(4270.88,5035) ; v1(4270.88,5215) 4270.88,5244.75 R14.2@4260,5255.63 4350,5345.63 4984.37,5345.63 5015,5315 6140.62,5315 v1(6174.99,5280.63) ; v1(4285.88,4475) 4285.88,4420 4400.88,4305 U3.8@4429.5,4305 ; v1(7729.99,4710.63) 7734.99,4710.63 8195.62,4250 H5.8@8445,4250
  Bottom Layer w10: v1(6174.99,5280.63) 6319.99,5425.63 ; H11.3@6340,5530 6340,5445.64 6319.99,5425.63 ; v1(7729.99,4710.63) 7340.62,5100 6799.32,5100 6473.69,5425.63 6319.99,5425.63
  Bottom Layer w20: v1(4260.88,4615) 4285.88,4590 v1(4285.88,4475) ; v1(4270.88,5035) v1(4270.88,5215)
CHRG_N: LED4.2 U3.7 | length 913.6
  Top Layer w10: LED4.2@3889.53,3605 3920,3605 4140.88,3825.88 v1(4140.88,3945) ; v1(4390.88,4235) 4410.88,4255 U3.7@4429.5,4255
  Bottom Layer w10: v1(4140.88,3945) 4160,3945 4390.88,4175.88 v1(4390.88,4235)
DB9_12V: DB1.9 F2.1 | length 475.7
  Top Layer w10: DB1.9@6341.42,3864.09 6344.36,3867.03 6361.12,3867.03 6455,3960.91 6455,4079.07 6454.44,4079.63 6454.44,4100.35 6531.12,4177.03 F2.1@6605,4177.03
DB9_12V_F: D2.2 F2.2 | length 295.2
  Top Layer w10: D2.2@6370,4177.62 6412.62,4177.62 6557.97,4322.97 F2.2@6605,4322.97
DB_COM: DB1.8 H10.1 | length 2085.9
  Top Layer w10: v1(5625.11,4876.45) 5653.75,4847.81 v1(5653.75,4724.99)
  Bottom Layer w10: v1(5625.11,4876.45) 5625.11,5511.77 H10.1@5643.33,5530 ; v1(5653.75,4724.99) 5653.75,4680.83 5810.49,4524.09 5930.91,4524.09 6450.49,4004.51 DB1.8@6450.48,3864.09
DB_DI0: DB1.6 H10.3 | length 2064.4
  Top Layer w10: v1(5918.6,4584.09) 5925,4590.5 5925,4675 5912.5,4687.5 5912.5,4717.5 5925,4730 5925,4962.69 v1(5918.6,4969.09)
  Bottom Layer w10: H10.3@5843.33,5530 5843.33,5044.36 v1(5918.6,4969.09) ; v1(5918.6,4584.09) 6458.6,4044.09 6508.6,4044.09 6558.6,3994.09 6558.6,3954.09 6648.6,3864.09 DB1.6@6668.59,3864.09
DB_DI1: DB1.7 H10.4 | length 2014
  Top Layer w10: v1(5943.33,5284.09) 5949.05,5278.37 v1(5949.05,4702.65) ; DB1.7@6559.53,3864.09 6559.54,4048.08 v1(6599.54,4088.08)
  Bottom Layer w10: v1(5943.33,5284.09) H10.4@5943.33,5530 ; v1(5949.05,4702.65) 5956.7,4695 6058.63,4695 6159.54,4594.09 6159.54,4530.46 6599.54,4090.46 v1(6599.54,4088.08)
DB_DO1: DB1.4 H11.4 | length 2258.8
  Inner2 w20: DB1.4@6395.94,3975.9 6410.9,3975.9 6487.78,4052.78 6512.78,4052.78 6530,4070 6530,4109.96 6650,4229.96 6650,4550 6760.79,4660.79 7030,4660.79 7050,4680.79 7050,4920 H11.4@6440,5530
DB_SHELL: DB1.10 DB1.11 R31.1 | length 1404.3
  Top Layer w10: DB1.11@6997.13,3920 6997.13,4112.75 R31.1@7070,4185.63
  Top Layer w30: DB1.10@6012.88,3920 6162.88,3770 6847.12,3770 DB1.11@6997.13,3920
DC_JACK: DC1.1 F1.1 | length 169.9
  Top Layer w50: F1.1@5560,4107.03 5562.48,4104.55 5562.48,3978.11 DC1.1@5562.48,3938.14
DC_JACK_F: D1.2 F1.2 | length 555.8
  Top Layer w25: F1.2@5560,4252.97 5697.03,4252.97 5780,4170 6076.61,4170 D1.2@6080,4173.39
